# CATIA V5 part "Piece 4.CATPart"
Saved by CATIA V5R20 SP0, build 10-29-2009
Part number: Piece 4
Bounding box of the stored display mesh (mm): x 10 to 20, y 216.374 to 282.11, z -20.417 to 310.758
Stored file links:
  C:\Users\Lambert\Desktop\IAO\Piece 4.CATPart
  C:\Users\Lambert\Desktop\IAO\Ass_Mon_IAO.CATProduct
  C:\Users\Lambert\Desktop\IAO\skl_general.CATPart
  C:\Users\Lambert\Desktop\IAO\Piece 3.CATPart
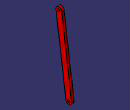
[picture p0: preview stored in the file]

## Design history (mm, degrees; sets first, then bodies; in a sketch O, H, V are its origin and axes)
Set1
  DatumPoint1 "E": linked copy from another document
  DatumPoint2 "F": linked copy from another document
Body1 (main body)
  Sketch1 on yz-plane, origin (0, 0, 0), H (0, 1, 0), V (0, 0, 1)
    construction line L1 (270.1143, -8.4178) -> (228.3698, 298.7587)
    point P1 (270.1143, -8.4178)
    point P2 (228.3698, 298.7587)
    line L2 (258.2236, -10.0337) -> (216.4791, 297.1428)
    line L3 (240.2605, 300.3747) -> (282.005, -6.8018)
    arc A1 centre (228.3698, 298.7587) radius 12 from (216.4791, 297.1428) to (240.2605, 300.3747) cw
    arc A2 centre (270.1143, -8.4178) radius 12 from (282.005, -6.8018) to (258.2236, -10.0337) cw
    reference projected point E1 (228.3698, 298.7587) from DatumPoint1
    reference projected point E2 (270.1143, -8.4178) from DatumPoint2
    distance L1 L2 = 12
    tangency: A1 L2, A2 L2, A1 L3, A2 L3
    coincidence: P2 E1, P1 E2
  Pad1: profile Sketch1, direction (1, 0, 0), length 20, opposite side length -10
  Sketch2 on end face of Pad1, origin (20, 241.4738, 179.3198), H (0, 1, 0), V (0, 0, 1)
    point P1 (-13.104, 119.4389)
    reference projected point E1 (-13.104, 119.4389) from DatumPoint1
    coincidence: P1 E1
  Hole1: placed by Sketch2, at (20, 228.3698, 298.7587) direction (-1, 0, 0), diameter 10, through (limit type 6)
  Sketch3 on end face of Pad1, origin (20, 260.7183, 71.4088), H (0, 1, 0), V (0, 0, 1)
    point P1 (9.396, -79.8265)
    reference projected point E1 (9.396, -79.8265) from DatumPoint2
    coincidence: P1 E1
  Hole2: placed by Sketch3, at (20, 270.1143, -8.4178) direction (-1, 0, 0), diameter 10, through (limit type 6)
